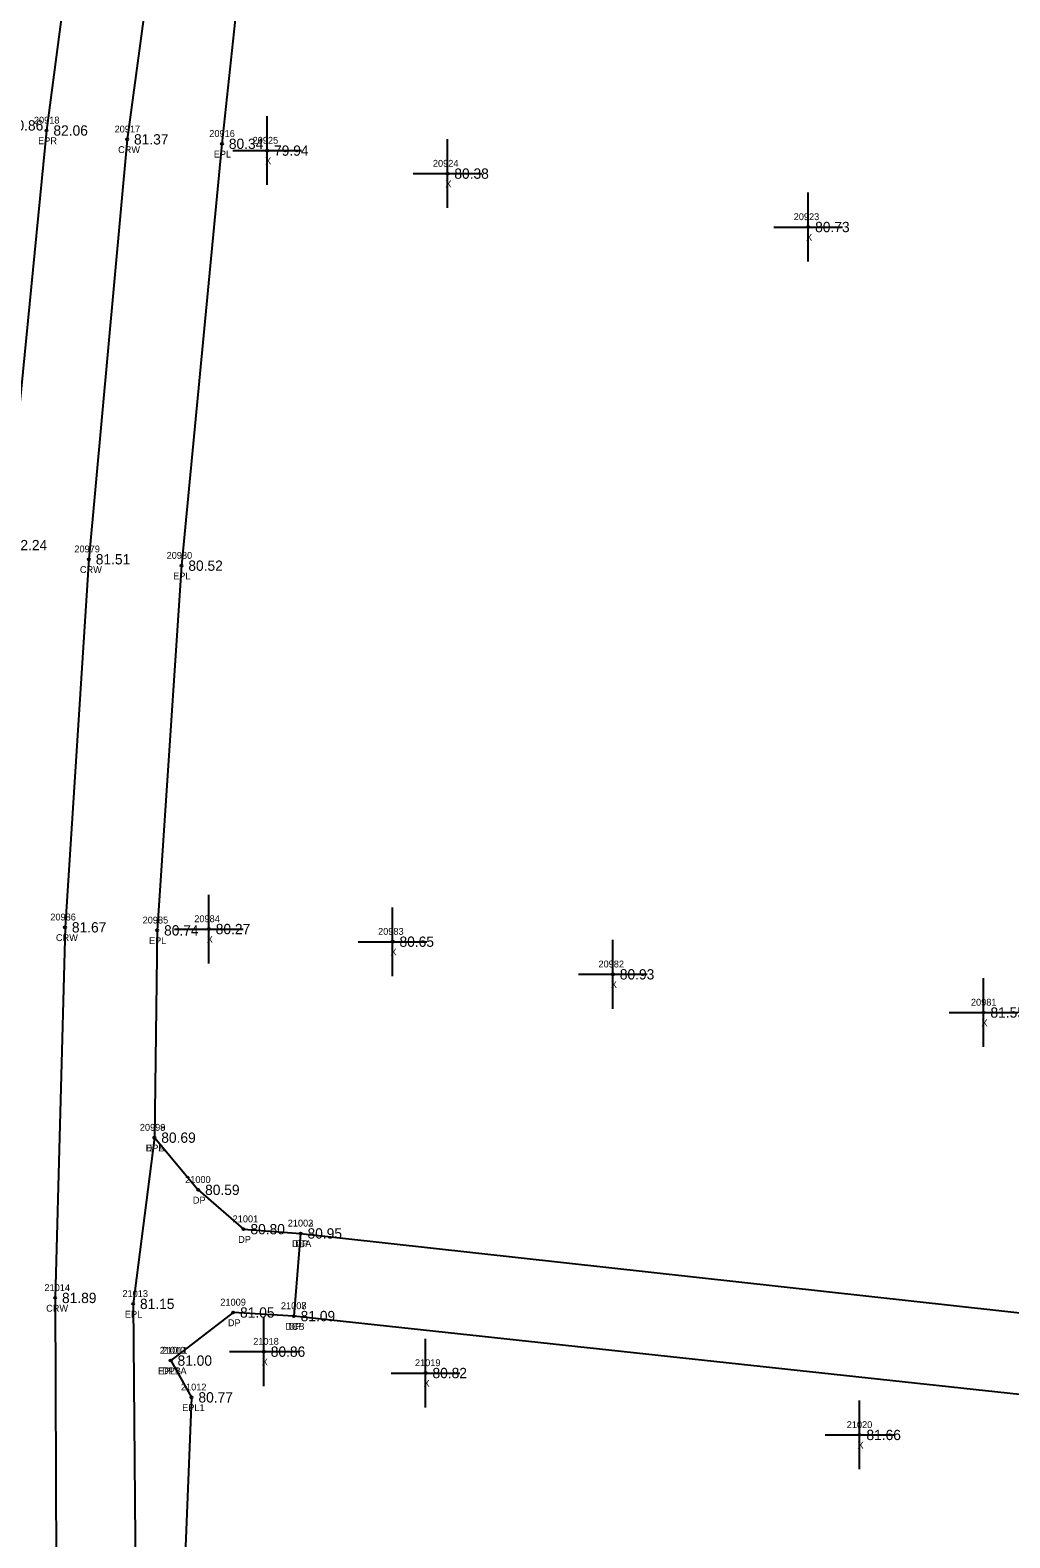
# Model space of a CAD drawing. Extents: x 2140110 to 2141565, y 506241 to 510327.
# Drawn here: x 2140568.4 to 2140711.1, y 507696.5 to 507916 of the extents above; entities that cross this region are included whole.
import ezdxf

# ---------------------------------------------------------------- set-up
doc = ezdxf.new("R2010")
doc.units = 0
for name, color, linetype in [('RD_DTM_BkLn1', 7, 'Continuous'), ('RD_EX_Conc', 7, 'Continuous'), ('RD_EX_Conc_txCode', 7, 'Continuous'), ('RD_EX_Driveway', 7, 'Continuous'), ('RD_EX_Driveway_txCode', 7, 'Continuous'), ('RD_EX_Misc', 7, 'Continuous'), ('RD_EX_Misc_txCode', 7, 'Continuous'), ('RD_EX_Road', 7, 'Continuous'), ('RD_EX_Road_txCode', 7, 'Continuous'), ('RD_EX_TX_Conc_ELEV', 7, 'Continuous'), ('RD_EX_TX_Driveway_ELEV', 7, 'Continuous'), ('RD_EX_TX_H2O_ELEV', 7, 'Continuous'), ('RD_EX_TX_Misc_ELEV', 7, 'Continuous'), ('RD_EX_TX_Road_ELEV', 7, 'Continuous'), ('RD_HC_Survey_ELEV', 7, 'Continuous'), ('RD_HC_Survey_txCode', 7, 'Continuous'), ('RD_SMD_Locator', 7, 'Continuous')]:
    doc.layers.add(name, color=color, linetype=linetype)

msp = doc.modelspace()

# ---------------------------------------------------------------- linework, layer by layer
at = {"layer": 'RD_DTM_BkLn1'}
msp.add_lwpolyline([(2140691.95, 508328.42), (2140672.34, 508274.49), (2140653.62, 508218.87), (2140636.66, 508164.77), (2140622.57, 508112.99), (2140609.87, 508060.1), (2140599.28, 508009.19), (2140590.24, 507956.73), (2140582.56, 507900.09), (2140577, 507838.97), (2140573.52, 507785.4), (2140572.08, 507731.46), (2140572.34, 507666.65)], dxfattribs=at)
at = {"layer": 'RD_EX_Conc'}
for p, q in [((2140607.82, 507740.85), (2140737.48, 507726.54)), ((2140735.65, 507714.92), (2140606.82, 507728.82))]:
    msp.add_line(p, q, dxfattribs=at)
at = {"layer": 'RD_EX_Driveway'}
msp.add_lwpolyline([(2140586.53, 507754.79), (2140592.91, 507747.19), (2140599.51, 507741.47), (2140607.82, 507740.85), (2140606.82, 507728.82), (2140598, 507729.34), (2140588.9, 507722.34)], dxfattribs=at)
at = {"layer": 'RD_EX_Misc'}
for p, q in [((2140602.95, 507893.45), (2140602.95, 507903.45)), ((2140629.19, 507890.1), (2140629.19, 507900.1)), ((2140597.95, 507898.45), (2140607.95, 507898.45)), ((2140624.19, 507895.1), (2140634.19, 507895.1)), ((2140681.71, 507882.33), (2140681.71, 507892.33)), ((2140676.71, 507887.33), (2140686.71, 507887.33)), ((2140594.46, 507780.15), (2140594.46, 507790.15)), ((2140621.21, 507778.31), (2140621.21, 507788.31)), ((2140589.46, 507785.15), (2140599.46, 507785.15)), ((2140616.21, 507783.31), (2140626.21, 507783.31)), ((2140653.28, 507773.56), (2140653.28, 507783.56)), ((2140648.28, 507778.56), (2140658.28, 507778.56)), ((2140707.23, 507768), (2140707.23, 507778)), ((2140702.23, 507773), (2140712.23, 507773)), ((2140602.47, 507718.64), (2140602.47, 507728.64)), ((2140597.47, 507723.64), (2140607.47, 507723.64)), ((2140626.01, 507715.53), (2140626.01, 507725.53)), ((2140621.01, 507720.53), (2140631.01, 507720.53)), ((2140689.18, 507706.52), (2140689.18, 507716.52)), ((2140684.18, 507711.52), (2140694.18, 507711.52))]:
    msp.add_line(p, q, dxfattribs=at)
at = {"layer": 'RD_EX_Road'}
for points in [[(2140681.68, 508333.39), (2140678, 508323.55), (2140662.26, 508279.8), (2140642.05, 508221.66), (2140625.62, 508169.11), (2140610.77, 508115.59), (2140598.26, 508062.62), (2140587.77, 508011.95), (2140578.4, 507958.88), (2140570.83, 507901.38), (2140564.91, 507841.03), (2140561.47, 507785.62), (2140559.81, 507732.33), (2140559.74, 507699.59), (2140559.81, 507681.93)], [(2140703.48, 508325.06), (2140698.7, 508311.25), (2140683.78, 508270.57), (2140664.74, 508214.51), (2140648.33, 508161.68), (2140633.75, 508109.58), (2140620.84, 508055.69), (2140611.2, 508005.95), (2140602.32, 507955.16), (2140596.37, 507899.44), (2140590.47, 507838.04), (2140586.94, 507784.96), (2140586.53, 507754.79), (2140583.43, 507730.59), (2140583.94, 507673.5)], [(2140588.9, 507722.34), (2140591.94, 507716.99), (2140590.96, 507692.84), (2140583.94, 507673.5)]]:
    msp.add_lwpolyline(points, dxfattribs=at)
at = {"layer": 'RD_SMD_Locator'}
for centre in [(2140570.83, 507901.38), (2140582.56, 507900.09), (2140596.37, 507899.44), (2140602.95, 507898.45), (2140629.19, 507895.1), (2140681.71, 507887.33), (2140577, 507838.97), (2140590.47, 507838.04), (2140573.52, 507785.4), (2140586.94, 507784.96), (2140594.46, 507785.15), (2140621.21, 507783.31), (2140653.28, 507778.56), (2140707.23, 507773), (2140586.53, 507754.79), (2140586.53, 507754.79), (2140592.91, 507747.19), (2140599.51, 507741.47), (2140607.82, 507740.85), (2140607.82, 507740.85), (2140572.08, 507731.46), (2140583.43, 507730.59), (2140598, 507729.34), (2140606.82, 507728.82), (2140606.82, 507728.82), (2140602.47, 507723.64), (2140588.9, 507722.34), (2140588.9, 507722.34), (2140626.01, 507720.53), (2140591.94, 507716.99), (2140689.18, 507711.52)]:
    msp.add_circle(centre, 0.15, dxfattribs=at)

# ---------------------------------------------------------------- texts
at = {"layer": 'RD_EX_Conc_txCode'}
for s, p in [('21003', (2140605.94, 507741.85)), ('DCA', (2140606.55, 507738.85)), ('21007', (2140604.95, 507729.82)), ('DCB', (2140605.57, 507726.82))]:
    msp.add_text(s, height=1, dxfattribs=at).set_placement(p)
at = {"layer": 'RD_EX_Driveway_txCode'}
for s, p in [('20999', (2140584.41, 507755.79)), ('DPA', (2140585.26, 507752.79)), ('21000', (2140591, 507748.19)), ('DP', (2140592.13, 507745.19)), ('21001', (2140597.92, 507742.47)), ('21002', (2140605.94, 507741.85)), ('DP', (2140598.73, 507739.47)), ('DP', (2140607.04, 507738.85)), ('21009', (2140596.13, 507730.34)), ('21008', (2140604.95, 507729.82)), ('DP', (2140597.23, 507727.34)), ('DP', (2140606.04, 507726.82)), ('21010', (2140587.31, 507723.34)), ('DPB', (2140587.65, 507720.34))]:
    msp.add_text(s, height=1, dxfattribs=at).set_placement(p)
at = {"layer": 'RD_EX_Misc_txCode'}
for s, p in [('20925', (2140600.83, 507899.45)), ('X', (2140602.64, 507896.45)), ('20924', (2140627.07, 507896.1)), ('X', (2140628.88, 507893.1)), ('20923', (2140679.59, 507888.33)), ('X', (2140681.39, 507885.33)), ('20984', (2140592.34, 507786.15)), ('20983', (2140619.09, 507784.31)), ('X', (2140594.15, 507783.15)), ('X', (2140620.89, 507781.31)), ('20982', (2140651.17, 507779.56)), ('X', (2140652.97, 507776.56)), ('20981', (2140705.39, 507774)), ('X', (2140706.91, 507771)), ('21018', (2140600.92, 507724.64)), ('X', (2140602.16, 507721.64)), ('21019', (2140624.46, 507721.53)), ('X', (2140625.7, 507718.53)), ('21020', (2140687.31, 507712.52)), ('X', (2140688.87, 507709.52))]:
    msp.add_text(s, height=1, dxfattribs=at).set_placement(p)
at = {"layer": 'RD_EX_Road_txCode'}
for s, p in [('20918', (2140568.99, 507902.38)), ('20916', (2140594.52, 507900.44)), ('EPR', (2140569.6, 507899.38)), ('EPL', (2140595.17, 507897.44)), ('20980', (2140588.31, 507839.04)), ('EPL', (2140589.26, 507836.04)), ('20985', (2140584.82, 507785.96)), ('EPL', (2140585.74, 507782.96)), ('20998', (2140584.41, 507755.79)), ('EPL', (2140585.33, 507752.79)), ('21013', (2140581.88, 507731.59)), ('EPL', (2140582.23, 507728.59)), ('21011', (2140587.64, 507723.34)), ('EPL1A', (2140587.05, 507720.34)), ('21012', (2140590.39, 507717.99)), ('EPL1', (2140590.57, 507714.99))]:
    msp.add_text(s, height=1, dxfattribs=at).set_placement(p)
at = {"layer": 'RD_EX_TX_Conc_ELEV'}
for s, p in [('80.95', (2140608.82, 507740.1)), ('81.09', (2140607.82, 507728.07))]:
    msp.add_text(s, height=1.5, dxfattribs=at).set_placement(p)
at = {"layer": 'RD_EX_TX_Driveway_ELEV'}
for s, p in [('80.69', (2140587.53, 507754.04)), ('80.59', (2140593.91, 507746.44)), ('80.80', (2140600.51, 507740.72)), ('80.95', (2140608.82, 507740.1)), ('81.05', (2140599, 507728.59)), ('81.09', (2140607.82, 507728.07)), ('81.00', (2140589.9, 507721.59))]:
    msp.add_text(s, height=1.5, dxfattribs=at).set_placement(p)
at = {"layer": 'RD_EX_TX_H2O_ELEV'}
msp.add_text('80.86', height=1.5, dxfattribs=at).set_placement((2140565.34, 507901.37))
at = {"layer": 'RD_EX_TX_Misc_ELEV'}
for s, p in [('79.94', (2140603.95, 507897.7)), ('80.38', (2140630.19, 507894.35)), ('80.73', (2140682.71, 507886.58)), ('80.27', (2140595.46, 507784.4)), ('80.65', (2140622.21, 507782.56)), ('80.93', (2140654.28, 507777.81)), ('81.55', (2140708.23, 507772.25)), ('80.86', (2140603.47, 507722.89)), ('80.82', (2140627.01, 507719.78)), ('81.66', (2140690.18, 507710.77))]:
    msp.add_text(s, height=1.5, dxfattribs=at).set_placement(p)
at = {"layer": 'RD_EX_TX_Road_ELEV'}
for s, p in [('82.06', (2140571.83, 507900.63)), ('80.34', (2140597.37, 507898.69)), ('82.24', (2140565.91, 507840.28)), ('80.52', (2140591.47, 507837.29)), ('80.74', (2140587.94, 507784.21)), ('80.69', (2140587.53, 507754.04)), ('81.15', (2140584.43, 507729.84)), ('81.00', (2140589.9, 507721.59)), ('80.77', (2140592.94, 507716.24))]:
    msp.add_text(s, height=1.5, dxfattribs=at).set_placement(p)
at = {"layer": 'RD_HC_Survey_ELEV'}
for s, p in [('81.37', (2140583.56, 507899.34)), ('81.51', (2140578, 507838.22)), ('81.67', (2140574.52, 507784.65)), ('81.89', (2140573.08, 507730.71))]:
    msp.add_text(s, height=1.5, dxfattribs=at).set_placement(p)
at = {"layer": 'RD_HC_Survey_txCode'}
for s, p in [('20917', (2140580.73, 507901.09)), ('CRW', (2140581.25, 507898.09)), ('20979', (2140574.88, 507839.97)), ('CRW', (2140575.69, 507836.97)), ('20986', (2140571.38, 507786.4)), ('CRW', (2140572.2, 507783.4)), ('21014', (2140570.53, 507732.46)), ('CRW', (2140570.77, 507729.46))]:
    msp.add_text(s, height=1, dxfattribs=at).set_placement(p)

doc.saveas('drawing.dxf')
